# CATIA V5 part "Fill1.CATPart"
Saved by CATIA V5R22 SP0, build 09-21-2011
Part number: Part1
Bounding box of the stored display mesh (mm): x -40 to 40, y -40 to 40, z 0 to 29.696
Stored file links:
  F:\CAT Parts and Products\R22\Fill1.CATPart
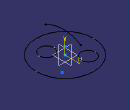
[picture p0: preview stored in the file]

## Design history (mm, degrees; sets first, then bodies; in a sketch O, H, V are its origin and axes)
Set1
  Circle1: type CtrRad, Start 0, End 180, Radius 40, Center {point type Coord, X 0, Y 0, Z 0}, Support xy-plane, FirstDirection (1, 0, 0)
  Circle2: type CtrRad, Start 0, End 180, Radius 10, Center {point type OnPlane, Support xy-plane, H -14.847, V 17.66, Direction (1, 0, 0)}, Support xy-plane, FirstDirection (1, 0, 0)
  Circle3: type CtrRad, Start 0, End 180, Radius 10, Center {point type OnPlane, Support xy-plane, H 8.94, V -16.749, Direction (1, 0, 0)}, Support xy-plane, FirstDirection (1, 0, 0)
  Point1: (0, 0, 10)
  Point2: (10, 10, 10)
  Point3: type OnPlane, Support xy-plane, H 22.759, V 19.049, Direction (1, 0, 0)
  Sketch1 on yz-plane, origin (0, 0, 0), H (0, 1, 0), V (0, 0, 1)
    spline S1 through (-27.0519, 23.0006) (0.9034, 29.6955) (22.0218, 23.0006)
Body1 (main body)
